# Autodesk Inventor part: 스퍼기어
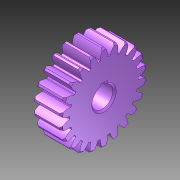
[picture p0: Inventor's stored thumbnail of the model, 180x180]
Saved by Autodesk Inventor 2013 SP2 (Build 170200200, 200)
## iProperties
Created: 2025-04
Part Number: 스퍼기어
Material: Generic
Document SubType Name: Modeling
Designer: 601
Density: 1 g/cm^3
Author: 601
변환 표준: STEP AP214IS
전처리기: Build: 200, Release: 2013 SP2 Update 6 - Date: Thu 07/17/2014
전송 단위: 밀리미터
불확실성: 0.01
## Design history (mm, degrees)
node "스퍼기어1"
node "솔리드1"
node "기준1"
